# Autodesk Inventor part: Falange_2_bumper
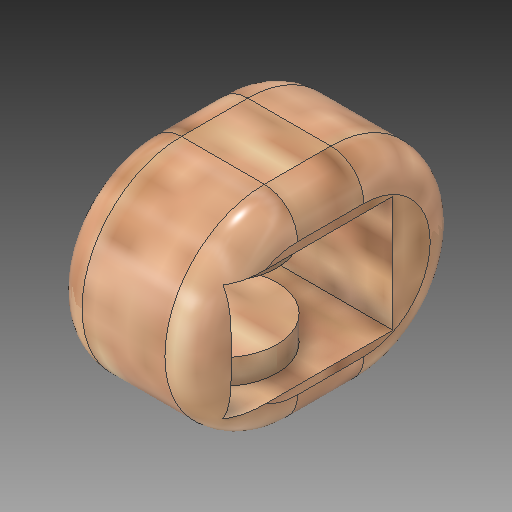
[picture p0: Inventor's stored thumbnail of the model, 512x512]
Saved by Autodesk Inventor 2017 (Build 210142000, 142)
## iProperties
Created: 2017-05
Part Number: Falange_2_bumper
Material: Generic
Document SubType Name: Modeling
Designer: alez_
Density: 1 g/cm^3
Appearance: Birch - Natural Polished
Author: alez_
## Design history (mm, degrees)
sketch "Sketch1"
  geometry: L1 (0, 0)-(9, 0); L2 (0, 0)-(0, -16); L3 (0, -16)-(9, -16); L4 (9, -16)-(9, 0)
  constraints: 8 end point, 2 perpendicular, 1 horizontal, 1 vertical
  dimensions: "d0" = 9 distance of L1.start L1.end; "d1" = 16 distance of L1.start L2.end
extrude "Extrusion1" new body sketch "Sketch1" distance "d2" = 12; taper "d3" = 0 deg
sketch "Sketch2"
  geometry: L1 (16, 0)-(14, 0); L2 (0, 0)-(16, 0) reference; L3 (14, 0)-(14, 2.5); L4 (14, 2.5)-(14, 9.5); L5 (14, 9.5)-(4.25, 9.5); L6 (0, 0)-(0, 12) reference; L7 (4.25, 9.5)-(4.25, 2.5); L8 (4.25, 2.5)-(14, 2.5)
  constraints: 12 end point, 3 perpendicular, 2 point on line, 1 parallel
  dimensions: "d4" = 2 distance of L1.start L1.end; "d5" = 2.5 distance of L1.end L3.end; "d6" = 7 distance of L3.end L4.end; "d7" = 9.75 distance of L4.end L5.end
extrude "Extrusion2" cut sketch "Sketch2" distance "d8" = 24; taper "d9" = 0 deg
sketch "Sketch3"
  geometry: L1 (0, 9.75)-(9, 9.75) reference; L2 (0, 0)-(9, 0) reference; L3 (4.5, 0)-(4.5, 5.75); C1 r 3.25 at (4.5, 5.75); 1 further point
  constraints: 2 end point, 1 centre point, 1 midpoint, 1 vertical
  dimensions: "d12" = 6.5 diameter of C1; "d21" = 5.75 distance of L3.start L3.end
extrude "Extrusion3" join sketch "Sketch3" distance "d13" = 1.5; taper "d14" = 0 deg
sketch "Sketch4"
  geometry: L1 (0, 0)-(9, 0) reference; L2 (0, 9.75)-(9, 9.75) reference; L3 (4.5, 9.75)-(4.5, 4); C1 r 3.25 at (4.5, 4); 1 further point
  constraints: 2 end point, 1 centre point, 1 midpoint, 1 vertical
  dimensions: "d16" = 6.5 diameter of C1; "d22" = 5.75 distance of L3.start L3.end
extrude "Extrusion4" join sketch "Sketch4" distance "d17" = 1.5; taper "d18" = 0 deg
fillet "Fillet2" dims "d19" = 6
fillet "Fillet3" dims "d20" = 6
fillet "Fillet4" dims "d23" = 2
body "Solid1"
